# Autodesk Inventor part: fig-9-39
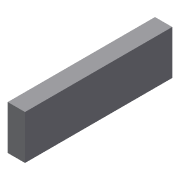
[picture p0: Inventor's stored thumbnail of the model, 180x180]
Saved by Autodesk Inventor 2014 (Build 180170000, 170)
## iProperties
Created: 2013-03
Part Number: fig-9-39
Material: Generic
Document SubType Name: Modeling
Designer: CADCIM
Density: 1 g/cm^3
Appearance: Default
Author: CADCIM
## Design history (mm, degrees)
sketch "Sketch1"
  geometry: L1 (-11.87, 2.655)-(7.31, 2.655); L2 (7.31, 2.655)-(7.31, -3.093); L3 (7.31, -3.093)-(-11.87, -3.093); L4 (-11.87, -3.093)-(-11.87, 2.655); 1 further point
  constraints: 8 end point, 2 parallel, 1 horizontal, 1 perpendicular
extrude "Extrusion1" new body sketch "Sketch1" distance "d0" = 2.25; taper "d1" = 0 deg
body "Solid1"
